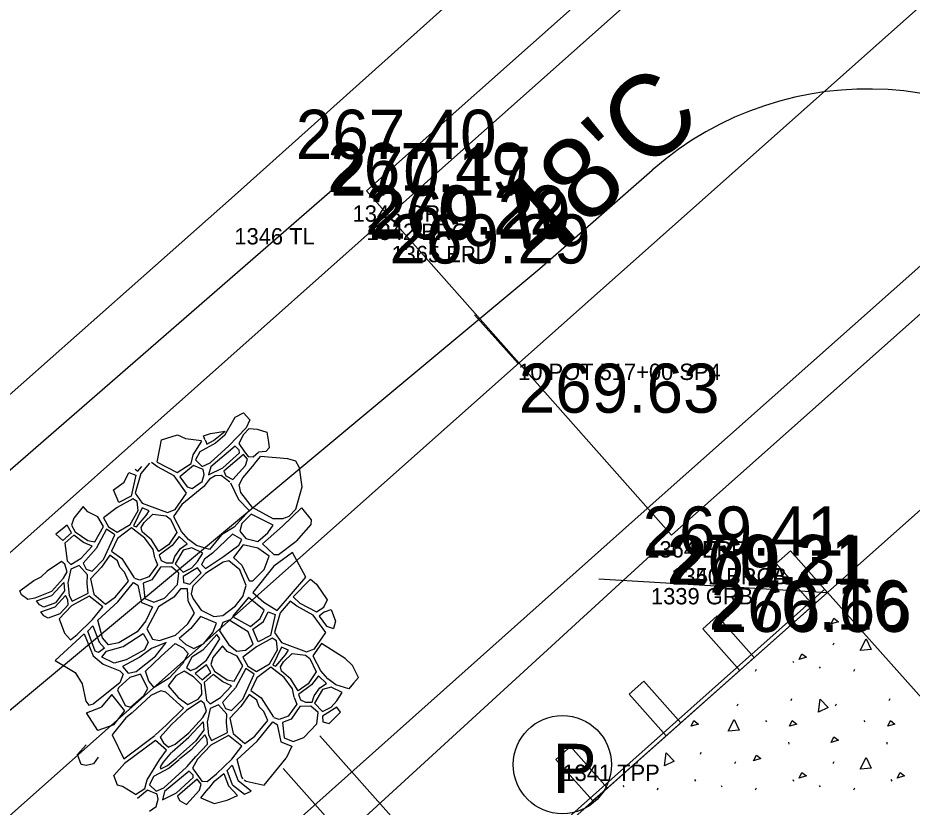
# Model space of a CAD drawing. Extents: x 49683 to 58852, y 49525 to 54803.
# Drawn here: x 53411.3 to 53465.9, y 51453.6 to 51501.8 of the extents above; entities that cross this region are included whole.
import ezdxf

# ---------------------------------------------------------------- set-up
doc = ezdxf.new("R2010")
doc.units = 0
for name, color, linetype in [('Level 1', 7, 'Continuous'), ('Level 11', 7, 'Continuous'), ('Level 15', 7, 'Continuous'), ('Level 16', 7, 'Continuous'), ('Level 18', 7, 'Continuous'), ('Level 27', 7, 'Continuous'), ('Level 3', 7, 'Continuous'), ('Level 32', 7, 'Continuous'), ('Level 48', 7, 'Continuous'), ('Level 5', 7, 'Continuous'), ('Level 51', 7, 'Continuous'), ('Level 53', 7, 'Continuous'), ('Level 55', 7, 'Continuous'), ('Level 57', 7, 'Continuous'), ('Level 59', 7, 'Continuous'), ('Level 61', 7, 'Continuous'), ('Level 7', 7, 'Continuous'), ('Level 8', 7, 'Continuous'), ('Level 9', 7, 'Continuous')]:
    doc.layers.add(name, color=color, linetype=linetype)

# ---------------------------------------------------------------- blocks, each defined once
blk = doc.blocks.new('TPP')
at = {"layer": 'Level 9'}
blk.add_circle((0, 0), 3, dxfattribs=at)
blk.add_text('P', height=3, dxfattribs=at).set_placement((-0.589, -1.729))

msp = doc.modelspace()

# ---------------------------------------------------------------- linework, layer by layer
at = {"layer": 'Level 1'}
for p, q in [((52544.807, 50683.302), (55534.583, 53340.862)), ((53441.831, 51480.651), (53439.174, 51483.64))]:
    msp.add_line(p, q, dxfattribs=at)
at = {"layer": 'Level 11'}
for p, q in [((53424.495, 51490.929), (53894.91, 51911.927)), ((53157.705, 51254.454), (53424.495, 51490.929))]:
    msp.add_line(p, q, dxfattribs=at)
at = {"layer": 'Level 15'}
for p, q in [((53460.734, 51466.679), (53909.18, 51865.296)), ((53446.758, 51467.502), (53460.734, 51466.679)), ((53445.785, 51453.392), (53460.734, 51466.679)), ((53460.734, 51466.679), (53489.966, 51433.793)), ((53461.076, 51463.466), (53461.131, 51463.591)), ((53456.338, 51461.856), (53456.394, 51461.981)), ((53458.608, 51462.481), (53458.663, 51462.398)), ((53460.227, 51462.128), (53460.282, 51462.045)), ((53462.338, 51461.856), (53462.394, 51461.981)), ((53455.214, 51459.747), (53455.27, 51459.872)), ((53458.503, 51460.066), (53458.558, 51460.191)), ((53461.214, 51459.747), (53461.27, 51459.872)), ((53464.503, 51460.066), (53464.558, 51460.191)), ((53456.949, 51458.859), (53457.004, 51458.776)), ((53462.949, 51458.859), (53463.004, 51458.776)), ((53458.351, 51457.528), (53458.365, 51457.403)), ((53464.351, 51457.528), (53464.365, 51457.403)), ((53452.967, 51456.792), (53453.022, 51456.917)), ((53449.076, 51456.223), (53449.131, 51456.348)), ((53455.076, 51456.223), (53455.131, 51456.348)), ((53461.076, 51456.223), (53461.131, 51456.348)), ((53448.227, 51454.885), (53448.282, 51454.802)), ((53452.608, 51455.238), (53452.663, 51455.155)), ((53454.227, 51454.885), (53454.282, 51454.802)), ((53458.608, 51455.238), (53458.663, 51455.155)), ((53460.227, 51454.885), (53460.282, 51454.802)), ((53464.608, 51455.238), (53464.663, 51455.155)), ((53450.338, 51454.614), (53450.394, 51454.738)), ((53456.338, 51454.614), (53456.394, 51454.738)), ((53462.338, 51454.614), (53462.394, 51454.738))]:
    msp.add_line(p, q, dxfattribs=at)
for points in [[(53460.959, 51464.75), (53461.126, 51465.096), (53461.403, 51464.888), (53460.959, 51464.75)], [(53462.724, 51463.124), (53463.099, 51463.831), (53463.39, 51463.179), (53462.738, 51463.124)], [(53458.994, 51462.578), (53459.161, 51462.925), (53459.438, 51462.716), (53458.994, 51462.578)], [(53460.174, 51459.36), (53460.284, 51460.153), (53460.781, 51459.64), (53460.187, 51459.364)], [(53452.406, 51458.499), (53452.572, 51458.846), (53452.85, 51458.637), (53452.406, 51458.499)], [(53454.663, 51458.209), (53455.037, 51458.916), (53455.329, 51458.264), (53454.676, 51458.209)], [(53458.406, 51458.499), (53458.572, 51458.846), (53458.85, 51458.637), (53458.406, 51458.499)], [(53464.406, 51458.499), (53464.572, 51458.846), (53464.85, 51458.637), (53464.406, 51458.499)], [(53460.959, 51457.507), (53461.126, 51457.854), (53461.403, 51457.646), (53460.959, 51457.507)], [(53450.764, 51456.08), (53450.874, 51456.873), (53451.371, 51456.359), (53450.777, 51456.084)], [(53456.219, 51456.393), (53456.385, 51456.74), (53456.663, 51456.532), (53456.219, 51456.393)], [(53462.724, 51455.881), (53463.099, 51456.589), (53463.39, 51455.937), (53462.738, 51455.881)], [(53458.994, 51455.335), (53459.161, 51455.682), (53459.438, 51455.474), (53458.994, 51455.335)], [(53464.994, 51455.335), (53465.161, 51455.682), (53465.438, 51455.474), (53464.994, 51455.335)]]:
    msp.add_lwpolyline(points, dxfattribs=at)
at = {"layer": 'Level 16'}
for points in [[(53423.906, 51476.272), (53424.54, 51477.389), (53425.048, 51477.635), (53425.431, 51477.211), (53425.212, 51476.738), (53424.15, 51475.623)], [(53419.774, 51474.638), (53420.049, 51475.996), (53421.011, 51476.305), (53421.505, 51476.078), (53422.48, 51475.952)], [(53423.906, 51476.272), (53423.332, 51475.787), (53422.376, 51475.271), (53422.118, 51474.769), (53422.534, 51474.377), (53423.012, 51474.586), (53424.15, 51475.623)], [(53422.706, 51476.017), (53422.657, 51476.113), (53422.6, 51476.232), (53423.028, 51476.388), (53423.932, 51476.522)], [(53422.706, 51475.987), (53422.768, 51475.86), (53422.817, 51475.737), (53423.222, 51475.946), (53423.932, 51476.522)], [(53423.892, 51476.496), (53423.823, 51476.436)], [(53425.396, 51476.679), (53425.061, 51476.326), (53424.759, 51475.778), (53425.115, 51475.265), (53425.327, 51474.986), (53425.64, 51474.964), (53425.977, 51475.236)], [(53425.396, 51476.679), (53425.882, 51476.657), (53426.479, 51476.472), (53426.578, 51475.854), (53426.619, 51475.506), (53426.409, 51475.273), (53425.977, 51475.236)], [(53419.774, 51474.638), (53421.002, 51473.995), (53421.848, 51474.548), (53421.983, 51475.075), (53422.499, 51475.911)], [(53419.318, 51474.573), (53418.784, 51473.932), (53418.428, 51472.743), (53418.856, 51472.118), (53420.399, 51471.557), (53420.877, 51471.741), (53421.576, 51472.734), (53420.806, 51473.799), (53419.802, 51474.337), (53419.43, 51474.621)], [(53425.732, 51474.528), (53426.088, 51474.974)], [(53427.636, 51471.257), (53427.84, 51471.332), (53428.252, 51471.752), (53428.641, 51473.134), (53428.481, 51474.289), (53428.24, 51474.688), (53427.763, 51474.831), (53426.088, 51474.974)], [(53418.425, 51474.198), (53418.601, 51474.091), (53418.843, 51474.374)], [(53427.636, 51471.257), (53427.457, 51471.172), (53426.869, 51471.171), (53425.61, 51471.862), (53424.897, 51472.785), (53424.782, 51473.237), (53425.014, 51473.678), (53425.716, 51474.513)], [(53424.225, 51473.402), (53423.685, 51473.815), (53423.33, 51473.802), (53422.974, 51473.593), (53422.631, 51473.152), (53421.282, 51472.048), (53420.766, 51471.312), (53421.243, 51470.417)], [(53424.251, 51473.376), (53424.739, 51472.355), (53425.39, 51471.684), (53424.486, 51470.654), (53423.698, 51470.202), (53422.972, 51469.288), (53422.175, 51469.539), (53421.693, 51469.916), (53421.269, 51470.39)], [(53427.434, 51470.718), (53428.601, 51471.851), (53429.191, 51471.107), (53429.166, 51470.814), (53428.272, 51469.805)], [(53427.434, 51470.718), (53426.206, 51469.648), (53426.898, 51468.998), (53427.192, 51468.999), (53428.272, 51469.805)], [(53419.626, 51468.794), (53419.526, 51469.289), (53419.025, 51469.987), (53418.217, 51470.623), (53417.346, 51469.973), (53416.99, 51469.2), (53417.615, 51468.748), (53418.377, 51467.558)], [(53413.322, 51466.741), (53414.059, 51467.556), (53414.283, 51467.936), (53414.138, 51468.394), (53413.937, 51468.573), (53413.054, 51467.979), (53412.691, 51467.635)], [(53419.641, 51468.767), (53419.803, 51468.361), (53419.265, 51467.633), (53418.727, 51467.432), (53418.404, 51467.529)], [(53413.322, 51466.741), (53412.307, 51466.32), (53411.874, 51466.236), (53411.491, 51466.525), (53411.39, 51466.774), (53412.245, 51467.408), (53412.691, 51467.635)], [(53428.092, 51466.414), (53429.135, 51467.477), (53429.514, 51467.175), (53430.165, 51466.214), (53429.931, 51465.747)], [(53413.335, 51466.485), (53414.081, 51467.288), (53414.114, 51466.763), (53413.568, 51466.048)], [(53413.568, 51466.048), (53412.848, 51465.776), (53412.582, 51465.922), (53412.401, 51466.155), (53413.335, 51466.485)], [(53413.827, 51465.372), (53414.347, 51465.925), (53414.314, 51466.227), (53414.169, 51466.484), (53413.547, 51465.793)], [(53414.485, 51463.775), (53414.893, 51464.105), (53415.821, 51465.011), (53416.448, 51465.793), (53415.622, 51466.44), (53414.537, 51465.847), (53413.79, 51465.058)], [(53428.092, 51466.414), (53428.485, 51466.022), (53429.514, 51465.484), (53429.951, 51465.769)], [(53413.827, 51465.372), (53413.117, 51465.104), (53412.851, 51465.251), (53412.67, 51465.483), (53413.547, 51465.793)], [(53429.998, 51465.496), (53429.673, 51465.227), (53430.113, 51464.615), (53430.558, 51464.478)], [(53429.998, 51465.496), (53430.4, 51465.627), (53430.681, 51464.927), (53430.558, 51464.478)], [(53413.79, 51465.058), (53414.125, 51464.18), (53414.485, 51463.775)], [(53415.322, 51464.139), (53413.551, 51462.519), (53414.771, 51461.79), (53415.186, 51461.097), (53415.427, 51460.037), (53415.603, 51459.797), (53415.879, 51459.868)], [(53415.322, 51464.139), (53415.866, 51462.802), (53416.487, 51462.287), (53417.498, 51461.887), (53417.709, 51461.677), (53417.487, 51461.16), (53415.879, 51459.868)], [(53429.812, 51463.563), (53429.278, 51462.8), (53429.754, 51461.905)], [(53431.767, 51461.133), (53432.076, 51461.469), (53431.703, 51462.217), (53431.255, 51462.635), (53429.812, 51463.563)], [(53428.137, 51460.282), (53428.038, 51460.777), (53427.536, 51461.475), (53426.729, 51462.111), (53425.858, 51461.461), (53425.502, 51460.689), (53426.126, 51460.236), (53426.889, 51459.046)], [(53431.767, 51461.133), (53431.484, 51460.776), (53430.686, 51461.027), (53430.204, 51461.405), (53429.781, 51461.879)], [(53417.126, 51458.58), (53417.796, 51459.435), (53417, 51460.442), (53416.351, 51459.66)], [(53419.655, 51457.948), (53420.346, 51458.584), (53421.387, 51459.602), (53420.315, 51460.584), (53420.002, 51460.673), (53419.399, 51460.382), (53418.26, 51459.342)], [(53428.152, 51460.255), (53428.315, 51459.849), (53427.776, 51459.122), (53427.239, 51458.921), (53426.915, 51459.017)], [(53417.126, 51458.58), (53416.158, 51458.244), (53415.465, 51459.325), (53416.351, 51459.66)], [(53418.243, 51459.325), (53417.872, 51459.006), (53417.037, 51457.976), (53417.746, 51456.507), (53419.637, 51457.931)], [(53420.685, 51456.935), (53421.72, 51457.837), (53422.592, 51458.776), (53422.625, 51458.251), (53422.122, 51457.592), (53421.596, 51457.111), (53421.006, 51456.596)], [(53425.037, 51455.282), (53424.948, 51455.388), (53424.664, 51456.473), (53425.878, 51457.581), (53426.838, 51458.773), (53427.112, 51458.604), (53427.332, 51457.54), (53427.996, 51457.278), (53427.661, 51456.545)], [(53418.456, 51454.332), (53419.031, 51454.707), (53419.166, 51455.234), (53419.915, 51456.448), (53420.344, 51457.049), (53419.683, 51457.636), (53417.788, 51456.223)], [(53421.597, 51456.024), (53422.143, 51456.653), (53422.859, 51457.414), (53422.826, 51457.715), (53422.681, 51457.972), (53421.864, 51457.066), (53421.141, 51456.48)], [(53416.176, 51456.612), (53415.878, 51456.206), (53415.432, 51456.1), (53415.128, 51456.172), (53414.906, 51456.769), (53415.444, 51457.372)], [(53420.66, 51456.91), (53420.147, 51456.313), (53419.951, 51456.019), (53420, 51455.897), (53420.404, 51456.105), (53420.987, 51456.578)], [(53425.1, 51455.223), (53425.209, 51455.139), (53426.307, 51454.909), (53427.661, 51456.545)], [(53418.456, 51454.332), (53417.664, 51454.826), (53417.361, 51454.898), (53417.139, 51455.495), (53417.788, 51456.223)], [(53421.116, 51456.455), (53420.514, 51455.946), (53419.558, 51455.431), (53419.3, 51454.928), (53419.716, 51454.536), (53420.194, 51454.745), (53421.571, 51456)], [(53424.371, 51454.915), (53424.052, 51455.798), (53424.358, 51456.125), (53424.722, 51455.173)], [(53422.914, 51454.687), (53423.304, 51455.175), (53423.841, 51455.608), (53424.143, 51454.867)], [(53421.578, 51453.73), (53422.363, 51454.588), (53422.474, 51454.968), (53422.229, 51455.262), (53421.027, 51454.232), (53421.149, 51453.962), (53421.578, 51453.73)], [(53423.255, 51453.786), (53424.062, 51453.976), (53424.684, 51454.276), (53424.143, 51454.867)], [(53424.371, 51454.915), (53425.119, 51454.348), (53425.522, 51454.542), (53424.722, 51455.173)], [(53419.299, 51453.322), (53419.715, 51453.605), (53419.838, 51454.046), (53419.778, 51454.353), (53419.19, 51454.597), (53418.567, 51454.082)], [(53422.448, 51454.137), (53422.899, 51454.672)], [(53422.448, 51454.137), (53423.255, 51453.786)]]:
    msp.add_lwpolyline(points, dxfattribs=at)
for points in [[(53424.545, 51475.604), (53423.049, 51474.353), (53422.913, 51473.851), (53423.784, 51474.28), (53424.802, 51475.2), (53424.789, 51475.36)], [(53425.046, 51475.103), (53423.845, 51474.072), (53423.967, 51473.803), (53424.395, 51473.57), (53425.18, 51474.429), (53425.291, 51474.809)], [(53418.037, 51473.992), (53418.466, 51473.833), (53418.182, 51472.546), (53417.435, 51472.166), (53417.105, 51472.937), (53417.755, 51473.416)], [(53421.161, 51473.738), (53421.601, 51473.126), (53421.92, 51473.029), (53422.533, 51473.446), (53422.656, 51473.887), (53422.595, 51474.193), (53422.007, 51474.438)], [(53418.293, 51472.387), (53417.324, 51471.859), (53416.502, 51471.234), (53416.808, 51470.683), (53417.335, 51470.352), (53418.119, 51470.819), (53418.623, 51471.689), (53418.55, 51472.228)], [(53416.502, 51470.694), (53416.147, 51471.294), (53415.535, 51471.588), (53415.266, 51471.931), (53414.677, 51471.219), (53414.542, 51470.79), (53414.762, 51470.374), (53415.533, 51469.848), (53415.974, 51469.775)], [(53418.868, 51471.837), (53418.327, 51470.733), (53418.511, 51470.672), (53419.112, 51471.371), (53419.284, 51471.666)], [(53420.973, 51470.344), (53420.483, 51469.609), (53419.882, 51469.179), (53419.441, 51469.889), (53418.866, 51470.366), (53418.805, 51470.648), (53418.989, 51470.955), (53419.517, 51471.458), (53420.337, 51471.348), (53420.594, 51471.14)], [(53426.869, 51470.793), (53425.526, 51471.463), (53424.958, 51470.875), (53424.832, 51470.413), (53425.199, 51469.962), (53425.933, 51469.795), (53426.543, 51470.32)], [(53414.286, 51470.774), (53413.593, 51470.237), (53414.005, 51469.846), (53414.553, 51470.305)], [(53414.687, 51470.171), (53414.139, 51469.69), (53414.272, 51468.595), (53414.507, 51468.383), (53415.144, 51468.775), (53415.815, 51469.491), (53415.268, 51469.725)], [(53416.676, 51470.531), (53416.049, 51469.368), (53415.255, 51468.462), (53415.445, 51468.094), (53415.802, 51467.983), (53416.496, 51468.676), (53417.19, 51470.196)], [(53424.947, 51469.899), (53424.37, 51470.224), (53423.151, 51469.067), (53422.678, 51468.7), (53422.489, 51468.384), (53422.74, 51468.133), (53423.833, 51468.869), (53424.757, 51469.563)], [(53421.115, 51470.094), (53420.684, 51469.537), (53419.907, 51468.948), (53420.022, 51468.623), (53420.337, 51468.476), (53420.725, 51468.487), (53420.862, 51468.876), (53421.199, 51469.359), (53421.619, 51469.633)], [(53422.563, 51469.067), (53421.902, 51469.391), (53421.366, 51469.254), (53420.883, 51468.414), (53421.365, 51467.911), (53421.9, 51468.174), (53422.247, 51468.563)], [(53426.615, 51468.882), (53425.933, 51469.375), (53425.041, 51469.573), (53424.442, 51468.806), (53424.945, 51468.345), (53425.395, 51467.39), (53425.626, 51467.391), (53426.309, 51468.074)], [(53428.048, 51469.109), (53426.907, 51468.287), (53425.619, 51466.68), (53426.292, 51466.081), (53427.112, 51465.579), (53428.854, 51467.615)], [(53416.887, 51468.956), (53416.372, 51468.218), (53415.701, 51467.502), (53415.912, 51466.575), (53416.615, 51465.961), (53417.23, 51466.398), (53418.025, 51467.371), (53417.791, 51467.918), (53417.501, 51468.208), (53417.356, 51468.599)], [(53424.147, 51468.596), (53423.801, 51468.522), (53422.729, 51467.828), (53421.952, 51467.051), (53421.857, 51466.599), (53421.982, 51466.284), (53422.464, 51465.592), (53423.23, 51465.205), (53423.797, 51465.268), (53424.554, 51465.857), (53425.006, 51466.435), (53425.206, 51467.096), (53424.829, 51468.062)], [(53415.02, 51468.317), (53414.506, 51468.093), (53414.327, 51467.266), (53414.404, 51466.495), (53414.593, 51466.149), (53415.566, 51466.63), (53415.5, 51467.211), (53415.523, 51467.748)], [(53419.982, 51468.224), (53419.444, 51467.454), (53418.917, 51467.243), (53419.021, 51466.294), (53419.579, 51466.074), (53420.222, 51466.317), (53421.014, 51467.15), (53421.109, 51467.857), (53420.646, 51468.235)], [(53422.247, 51468.185), (53421.365, 51467.638), (53421.385, 51467.281), (53421.773, 51467.187), (53422.467, 51467.88)], [(53418.327, 51467.284), (53418.6, 51467.116), (53418.821, 51466.052), (53419.484, 51465.789), (53419.093, 51464.935), (53418.555, 51464.27), (53417.437, 51463.595), (53416.794, 51463.478), (53416.436, 51463.899), (53416.153, 51464.984), (53417.366, 51466.092)], [(53421.193, 51466.887), (53420.792, 51466.381), (53419.853, 51465.8), (53419.145, 51464.461), (53419.492, 51463.818), (53419.924, 51463.745), (53420.905, 51464.073), (53421.643, 51464.748), (53422.066, 51465.402), (53421.666, 51466.139), (53421.625, 51466.898)], [(53425.349, 51466.361), (53424.38, 51465.196), (53425.482, 51464.585), (53426.07, 51465.076), (53426.316, 51465.59)], [(53430.088, 51464.223), (53429.317, 51465.288), (53428.313, 51465.826), (53427.897, 51466.144), (53427.296, 51465.42), (53426.939, 51464.231), (53427.367, 51463.607), (53428.91, 51463.045), (53429.388, 51463.229)], [(53426.549, 51465.481), (53426.977, 51465.322), (53426.694, 51464.035), (53425.946, 51463.654), (53425.616, 51464.426), (53426.266, 51464.904)], [(53422.424, 51465.213), (53421.833, 51464.474), (53421.126, 51463.852), (53421.526, 51463.494), (53422.011, 51463.242), (53422.622, 51463.558), (53423.171, 51464.234), (53423.393, 51464.792)], [(53425.652, 51463.507), (53425.334, 51464.266), (53424.171, 51464.988), (53423.779, 51464.84), (53423.582, 51464.325), (53424.157, 51463.481), (53424.635, 51463.077), (53425.174, 51463.151)], [(53415.847, 51464.636), (53416.225, 51463.646), (53416.562, 51463.267), (53416.193, 51463.003), (53415.982, 51463.087), (53415.541, 51464.309)], [(53418.924, 51464.176), (53419.229, 51463.639), (53418.996, 51463.175), (53417.879, 51462.562), (53417.151, 51462.361), (53416.393, 51462.719), (53416.688, 51463.077), (53417.69, 51463.363)], [(53420.335, 51463.609), (53419.429, 51463.249), (53418.722, 51462.711), (53417.657, 51462.151), (53418.015, 51461.751), (53418.5, 51461.836), (53419.681, 51462.786)], [(53423.414, 51464.106), (53422.575, 51463.156), (53421.893, 51462.719), (53421.579, 51462.093), (53421.814, 51461.904), (53422.138, 51462.027), (53422.798, 51462.531), (53423.615, 51463.839)], [(53426.804, 51463.876), (53425.836, 51463.348), (53425.014, 51462.722), (53425.32, 51462.171), (53425.846, 51461.841), (53426.631, 51462.307), (53427.134, 51463.178), (53427.061, 51463.717)], [(53420.873, 51463.556), (53421.368, 51463.294), (53421.662, 51462.936), (53421.324, 51462.303), (53420.501, 51461.438), (53419.594, 51460.868), (53419.268, 51461.257), (53419.058, 51461.868), (53420.029, 51462.776)], [(53425.013, 51462.183), (53424.659, 51462.783), (53424.046, 51463.076), (53423.777, 51463.419), (53423.188, 51462.708), (53423.053, 51462.279), (53423.273, 51461.862), (53424.044, 51461.337), (53424.485, 51461.263)], [(53427.379, 51463.325), (53426.839, 51462.222), (53427.023, 51462.161), (53427.624, 51462.86), (53427.796, 51463.154)], [(53429.485, 51461.833), (53428.994, 51461.097), (53428.393, 51460.668), (53427.953, 51461.378), (53427.378, 51461.855), (53427.317, 51462.137), (53427.501, 51462.443), (53428.028, 51462.946), (53428.849, 51462.837), (53429.106, 51462.629)], [(53422.797, 51462.262), (53422.104, 51461.725), (53422.517, 51461.335), (53423.065, 51461.793)], [(53425.188, 51462.019), (53424.561, 51460.857), (53423.767, 51459.951), (53423.956, 51459.582), (53424.314, 51459.471), (53425.007, 51460.164), (53425.702, 51461.685)], [(53418.752, 51461.689), (53418.099, 51461.477), (53417.434, 51460.876), (53417.35, 51460.728), (53417.812, 51459.759), (53418.149, 51459.675), (53418.962, 51460.382), (53419.204, 51460.815)], [(53422.516, 51460.441), (53422.494, 51461.022), (53421.992, 51461.524), (53421.434, 51461.859), (53420.908, 51461.579), (53420.439, 51460.975), (53421.063, 51460.261), (53421.644, 51459.837), (53422.281, 51460.161)], [(53423.199, 51461.66), (53422.651, 51461.178), (53422.784, 51460.084), (53423.018, 51459.872), (53423.655, 51460.263), (53424.326, 51460.979), (53423.779, 51461.213)], [(53429.627, 51461.582), (53429.196, 51461.025), (53428.418, 51460.437), (53428.534, 51460.111), (53428.848, 51459.965), (53429.237, 51459.976), (53429.374, 51460.364), (53429.71, 51460.848), (53430.13, 51461.121)], [(53431.074, 51460.555), (53430.413, 51460.88), (53429.878, 51460.743), (53429.394, 51459.903), (53429.876, 51459.399), (53430.412, 51459.662), (53430.759, 51460.051)], [(53425.398, 51460.444), (53424.884, 51459.706), (53424.213, 51458.99), (53424.424, 51458.063), (53425.127, 51457.45), (53425.742, 51457.886), (53426.536, 51458.859), (53426.302, 51459.406), (53426.012, 51459.696), (53425.867, 51460.087)], [(53422.449, 51460.061), (53421.565, 51459.468), (53420.659, 51458.607), (53419.954, 51457.835), (53420.166, 51457.489), (53420.468, 51457.232), (53420.881, 51457.4), (53421.72, 51458.105), (53422.57, 51459.044), (53422.794, 51459.425), (53422.649, 51459.883)], [(53423.532, 51459.805), (53423.018, 51459.581), (53422.838, 51458.754), (53422.915, 51457.983), (53423.105, 51457.637), (53424.077, 51458.119), (53424.011, 51458.7), (53424.034, 51459.236)], [(53428.494, 51459.713), (53427.955, 51458.943), (53427.428, 51458.731), (53427.533, 51457.783), (53428.091, 51457.562), (53428.734, 51457.805), (53429.525, 51458.639), (53429.621, 51459.345), (53429.158, 51459.724)], [(53430.758, 51459.673), (53429.876, 51459.126), (53429.897, 51458.769), (53430.285, 51458.675), (53430.979, 51459.369)], [(53424.959, 51457.282), (53424.133, 51457.929), (53423.049, 51457.336), (53422.243, 51456.486), (53421.941, 51455.938), (53422.298, 51455.424), (53422.51, 51455.145), (53422.823, 51455.123), (53423.404, 51455.593), (53424.333, 51456.499)], [(53421.727, 51455.764), (53420.231, 51454.512), (53420.096, 51454.01), (53420.966, 51454.44), (53421.984, 51455.36), (53421.972, 51455.519)]]:
    msp.add_lwpolyline(points, close=True, dxfattribs=at)
at = {"layer": 'Level 18'}
for p, q in [((53443.152, 51486.459), (53450.017, 51492.472)), ((53395.485, 51446.762), (53443.152, 51486.459))]:
    msp.add_line(p, q, dxfattribs=at)
msp.add_arc((53463.195, 51477.428), 20, 41.6334, 131.2163, dxfattribs=at)
at = {"layer": 'Level 27'}
for p, q in [((53457.592, 51468.436), (53458.475, 51469.221)), ((53458.475, 51469.221), (53460.734, 51466.679)), ((53459.85, 51465.894), (53457.592, 51468.436)), ((53418.518, 51429.489), (53460.568, 51466.866)), ((53418.684, 51429.302), (53460.734, 51466.679)), ((53460.734, 51466.679), (53459.85, 51465.894)), ((53453.107, 51464.45), (53453.991, 51465.235)), ((53453.991, 51465.235), (53456.249, 51462.693)), ((53455.366, 51461.908), (53453.107, 51464.45)), ((53456.249, 51462.693), (53455.366, 51461.908)), ((53448.623, 51460.464), (53449.506, 51461.249)), ((53449.506, 51461.249), (53451.765, 51458.707)), ((53450.881, 51457.922), (53448.623, 51460.464)), ((53451.765, 51458.707), (53450.881, 51457.922)), ((53444.138, 51456.477), (53445.022, 51457.262)), ((53445.022, 51457.262), (53447.28, 51454.721)), ((53446.397, 51453.936), (53444.138, 51456.477)), ((53447.28, 51454.721), (53446.397, 51453.936))]:
    msp.add_line(p, q, dxfattribs=at)
at = {"layer": 'Level 3'}
for p, q in [((53434.092, 51489.844), (53883.273, 51889.178)), ((53449.718, 51471.806), (53898.742, 51870.567)), ((53162.497, 51248.316), (53434.092, 51489.844)), ((53179.352, 51230.724), (53449.718, 51471.806))]:
    msp.add_line(p, q, dxfattribs=at)
at = {"layer": 'Level 5'}
for p, q in [((53432.563, 51491.203), (53881.993, 51890.68)), ((53900.074, 51869.402), (53451.19, 51470.163)), ((53451.19, 51470.163), (53432.563, 51491.203))]:
    msp.add_line(p, q, dxfattribs=at)
at = {"layer": 'Level 7'}
for p, q in [((53431.716, 51492.319), (53399.953, 51464.721)), ((53424.8, 51445.953), (53449.946, 51468.944))]:
    msp.add_line(p, q, dxfattribs=at)
at = {"layer": 'Level 8'}
for p, q in [((53439.059, 51447.413), (53429.719, 51457.92)), ((53436.816, 51445.42), (53427.484, 51455.918))]:
    msp.add_line(p, q, dxfattribs=at)

# ---------------------------------------------------------------- block references
at = {"layer": 'Level 9'}
msp.add_blockref('TPP', (53444.535, 51456.156), dxfattribs=at)

# ---------------------------------------------------------------- texts
at = {"layer": 'Level 32'}
for s, p in [('267.40', (53428.244, 51493.16)), ('267.49', (53430.166, 51491.13)), ('270.17', (53430.349, 51490.907)), ('270.22', (53432.485, 51488.533)), ('269.29', (53432.76, 51488.284)), ('269.29', (53433.972, 51486.767)), ('269.63', (53441.864, 51477.651)), ('269.41', (53449.432, 51468.924)), ('270.21', (53450.906, 51467.197)), ('269.31', (53451.16, 51467.144)), ('270.16', (53453.467, 51464.409)), ('266.66', (53453.602, 51464.261))]:
    msp.add_text(s, height=3, dxfattribs=at).set_placement(p)
at = {"layer": 'Level 48'}
msp.add_text("48'C", height=5, rotation=41.6334, dxfattribs=at).set_placement((53443.152, 51486.459))
at = {"layer": 'Level 51'}
msp.add_text('10 POT 517+00 SP4', height=1, dxfattribs=at).set_placement((53441.83, 51479.65))
at = {"layer": 'Level 53'}
for s, p in [('1365 EPL', (53434.092, 51486.844)), ('1364 EPR', (53449.718, 51468.806))]:
    msp.add_text(s, height=1, dxfattribs=at).set_placement(p)
at = {"layer": 'Level 55'}
for s, p in [('1342 BRC', (53432.563, 51488.203)), ('1340 BRCA', (53451.19, 51467.163)), ('1351 BRCB', (53451.19, 51467.163))]:
    msp.add_text(s, height=1, dxfattribs=at).set_placement(p)
at = {"layer": 'Level 57'}
for s, p in [('1343 GRA', (53431.716, 51489.319)), ('1339 GRB', (53449.946, 51465.944))]:
    msp.add_text(s, height=1, dxfattribs=at).set_placement(p)
at = {"layer": 'Level 59'}
msp.add_text('1341 TPP', height=1, dxfattribs=at).set_placement((53444.535, 51455.156))
at = {"layer": 'Level 61'}
msp.add_text('1346 TL', height=1, dxfattribs=at).set_placement((53424.495, 51487.929))

doc.saveas('drawing.dxf')
